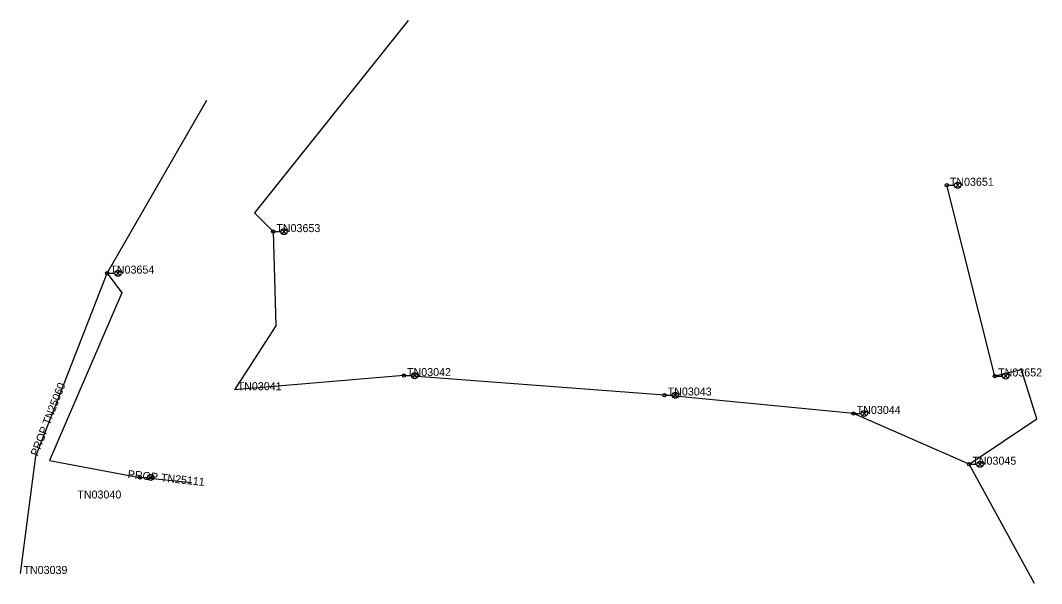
# Model space of a CAD drawing. Extents: x -444502 to -444311, y -1121026 to -1120921.
import ezdxf

# ---------------------------------------------------------------- set-up
doc = ezdxf.new("R2010")
doc.units = 0
for name, color, linetype in [('Kabelove_vedeni_zemni', 7, 'Continuous'), ('Propojovaci_kabel', 7, 'Continuous'), ('Propojovaci_kabel_popis', 7, 'Continuous'), ('Verejne_osvetleni', 7, 'Continuous'), ('Verejne_osvetleni_popis', 7, 'Continuous')]:
    doc.layers.add(name, color=color, linetype=linetype)

msp = doc.modelspace()

# ---------------------------------------------------------------- linework, layer by layer
at = {"layer": 'Kabelove_vedeni_zemni'}
for points in [[(-444429.42, -1120920.74), (-444458.22, -1120956.83), (-444454.72, -1120960.33)], [(-444485.87, -1120968.14), (-444467.17, -1120935.72)], [(-444319.42, -1120987.43), (-444328.44, -1120951.63)], [(-444454.72, -1120960.33), (-444454.27, -1120978.03), (-444462, -1120989.99)], [(-444485.87, -1120968.14), (-444483.09, -1120971.81), (-444496.65, -1121003.27), (-444479.72, -1121006.43)], [(-444430.23, -1120987.34), (-444462, -1120989.99)], [(-444381.38, -1120991.01), (-444430.23, -1120987.34)], [(-444324.25, -1121003.96), (-444311.56, -1120995.41), (-444314.44, -1120986.24), (-444319.42, -1120987.43)], [(-444345.93, -1120994.44), (-444381.38, -1120991.01)], [(-444324.25, -1121003.96), (-444345.93, -1120994.44)], [(-444312.02, -1121026.33), (-444324.25, -1121003.96)]]:
    msp.add_lwpolyline(points, dxfattribs=at)
at = {"layer": 'Propojovaci_kabel'}
for points in [[(-444502.13, -1121024.42), (-444499.23, -1121002.41), (-444485.87, -1120968.14)], [(-444470.05, -1121007.44), (-444479.72, -1121006.43)]]:
    msp.add_lwpolyline(points, dxfattribs=at)
at = {"layer": 'Verejne_osvetleni'}
for p, q in [((-444326.01, -1120951.22), (-444326.82, -1120952.04)), ((-444326.01, -1120952.04), (-444326.82, -1120951.22)), ((-444328.13, -1120951.63), (-444326.98, -1120951.63)), ((-444454.41, -1120960.33), (-444453.27, -1120960.33)), ((-444452.29, -1120959.93), (-444453.1, -1120960.74)), ((-444452.29, -1120960.74), (-444453.1, -1120959.93)), ((-444485.56, -1120968.14), (-444484.42, -1120968.14)), ((-444483.44, -1120967.73), (-444484.25, -1120968.54)), ((-444483.44, -1120968.54), (-444484.25, -1120967.73)), ((-444429.92, -1120987.34), (-444428.78, -1120987.34)), ((-444427.8, -1120986.94), (-444428.61, -1120987.75)), ((-444427.8, -1120987.75), (-444428.61, -1120986.94)), ((-444319.12, -1120987.43), (-444317.97, -1120987.43)), ((-444316.99, -1120987.02), (-444317.8, -1120987.83)), ((-444316.99, -1120987.83), (-444317.8, -1120987.02)), ((-444381.08, -1120991.01), (-444379.93, -1120991.01)), ((-444378.95, -1120990.6), (-444379.76, -1120991.41)), ((-444378.95, -1120991.41), (-444379.76, -1120990.6)), ((-444345.63, -1120994.44), (-444344.48, -1120994.44)), ((-444343.5, -1120994.04), (-444344.31, -1120994.85)), ((-444343.5, -1120994.85), (-444344.31, -1120994.04)), ((-444323.94, -1121003.96), (-444322.79, -1121003.96)), ((-444321.82, -1121003.56), (-444322.63, -1121004.37)), ((-444321.82, -1121004.37), (-444322.63, -1121003.56)), ((-444479.41, -1121006.43), (-444478.26, -1121006.43)), ((-444477.29, -1121006.02), (-444478.1, -1121006.83)), ((-444477.29, -1121006.83), (-444478.1, -1121006.02))]:
    msp.add_line(p, q, dxfattribs=at)
for centre, radius in [((-444328.44, -1120951.63), 0.306), ((-444326.41, -1120951.63), 0.574), ((-444454.72, -1120960.33), 0.306), ((-444452.69, -1120960.33), 0.574), ((-444485.87, -1120968.14), 0.306), ((-444483.84, -1120968.14), 0.574), ((-444430.23, -1120987.34), 0.306), ((-444428.2, -1120987.34), 0.574), ((-444319.42, -1120987.43), 0.306), ((-444317.4, -1120987.43), 0.574), ((-444381.38, -1120991.01), 0.306), ((-444379.36, -1120991.01), 0.574), ((-444345.93, -1120994.44), 0.306), ((-444343.91, -1120994.44), 0.574), ((-444324.25, -1121003.96), 0.306), ((-444322.22, -1121003.96), 0.574), ((-444479.72, -1121006.43), 0.306), ((-444477.69, -1121006.43), 0.574)]:
    msp.add_circle(centre, radius, dxfattribs=at)

# ---------------------------------------------------------------- texts
at = {"layer": 'Propojovaci_kabel_popis'}
for s, rotation, p in [('PROP TN25060', 68.7251, (-444498.91, -1121002.54)), ('PROP TN25111', 354.0347, (-444482.07, -1121006.53))]:
    msp.add_text(s, height=1.5, rotation=rotation, dxfattribs=at).set_placement(p)
at = {"layer": 'Verejne_osvetleni_popis'}
for s, p in [('TN03651', (-444327.88, -1120951.74)), ('TN03653', (-444454.15, -1120960.43)), ('TN03654', (-444485.28, -1120968.21)), ('TN03042', (-444429.65, -1120987.43)), ('TN03652', (-444318.82, -1120987.49)), ('TN03041', (-444461.41, -1120990.07)), ('TN03043', (-444380.78, -1120991.07)), ('TN03044', (-444345.34, -1120994.52)), ('TN03045', (-444323.66, -1121004.04)), ('TN03040', (-444491.47, -1121010.38)), ('TN03039', (-444501.57, -1121024.53))]:
    msp.add_text(s, height=1.5, dxfattribs=at).set_placement(p)

doc.saveas('drawing.dxf')
